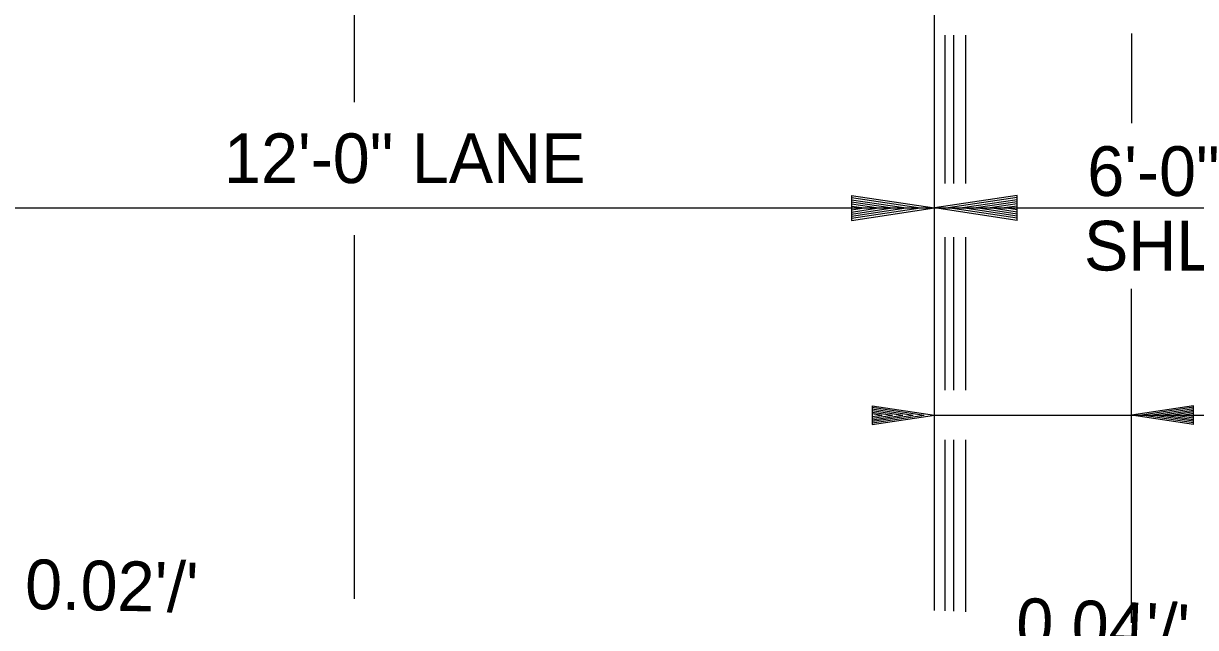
# Model space of a CAD drawing. Extents: x 2263886 to 2266026, y -3122850 to -3121850.
# Drawn here: x 2265509.57 to 2265523.72, y -3122285.03 to -3122277.73 of the extents above; entities that cross this region are included whole.
import ezdxf

# ---------------------------------------------------------------- set-up
doc = ezdxf.new("R2010")
doc.units = 0
doc.layers.add('R_Border Prem', color=7, linetype='Continuous')

msp = doc.modelspace()

# ---------------------------------------------------------------- linework, layer by layer
at = {"layer": 'R_Border Prem'}
for p, q in [((2265513.565, -3122260.962), (2265513.565, -3122278.683)), ((2265520.568, -3122281.934), (2265520.568, -3122276.962)), ((2265520.694, -3122277.875), (2265520.694, -3122279.667)), ((2265520.799, -3122277.875), (2265520.799, -3122279.667)), ((2265520.948, -3122279.667), (2265520.948, -3122277.875)), ((2265522.948, -3122277.857), (2265522.948, -3122278.937)), ((2265519.568, -3122279.812), (2265520.568, -3122279.962)), ((2265519.568, -3122279.812), (2265519.568, -3122280.112)), ((2265519.568, -3122279.837), (2265520.401, -3122279.962)), ((2265519.568, -3122279.863), (2265520.229, -3122279.962)), ((2265519.568, -3122279.888), (2265520.062, -3122279.962)), ((2265521.568, -3122279.812), (2265520.568, -3122279.962)), ((2265521.568, -3122279.837), (2265520.735, -3122279.962)), ((2265521.568, -3122279.863), (2265520.907, -3122279.962)), ((2265521.568, -3122279.888), (2265521.073, -3122279.962)), ((2265521.568, -3122280.112), (2265521.568, -3122279.812)), ((2265508.568, -3122279.962), (2265520.568, -3122279.962)), ((2265519.568, -3122279.914), (2265519.893, -3122279.962)), ((2265519.568, -3122279.939), (2265519.726, -3122279.962)), ((2265519.568, -3122280.112), (2265520.568, -3122279.962)), ((2265519.568, -3122280.011), (2265519.893, -3122279.962)), ((2265519.568, -3122280.062), (2265520.229, -3122279.962)), ((2265519.568, -3122280.087), (2265520.401, -3122279.962)), ((2265519.568, -3122280.037), (2265520.062, -3122279.962)), ((2265519.568, -3122279.986), (2265519.726, -3122279.962)), ((2265521.568, -3122280.112), (2265520.568, -3122279.962)), ((2265520.568, -3122279.962), (2265526.568, -3122279.962)), ((2265521.568, -3122280.087), (2265520.735, -3122279.962)), ((2265521.568, -3122280.062), (2265520.907, -3122279.962)), ((2265521.568, -3122280.037), (2265521.073, -3122279.962)), ((2265521.568, -3122279.913), (2265521.243, -3122279.962)), ((2265521.568, -3122280.011), (2265521.243, -3122279.962)), ((2265521.568, -3122279.939), (2265521.41, -3122279.962)), ((2265521.568, -3122279.986), (2265521.41, -3122279.962)), ((2265513.565, -3122280.29), (2265513.565, -3122283.962)), ((2265520.694, -3122280.315), (2265520.694, -3122282.162)), ((2265520.799, -3122280.315), (2265520.799, -3122282.162)), ((2265520.948, -3122282.162), (2265520.948, -3122280.315)), ((2265522.948, -3122284.972), (2265522.948, -3122280.937)), ((2265520.568, -3122284.822), (2265520.568, -3122281.934)), ((2265519.818, -3122282.35), (2265520.568, -3122282.462)), ((2265519.818, -3122282.35), (2265519.818, -3122282.575)), ((2265519.818, -3122282.368), (2265520.443, -3122282.462)), ((2265519.818, -3122282.388), (2265520.314, -3122282.462)), ((2265519.818, -3122282.406), (2265520.189, -3122282.462)), ((2265519.818, -3122282.426), (2265520.062, -3122282.462)), ((2265519.818, -3122282.445), (2265519.936, -3122282.462)), ((2265523.698, -3122282.35), (2265522.948, -3122282.462)), ((2265523.698, -3122282.368), (2265523.074, -3122282.462)), ((2265523.698, -3122282.388), (2265523.203, -3122282.462)), ((2265523.698, -3122282.406), (2265523.327, -3122282.462)), ((2265523.698, -3122282.425), (2265523.455, -3122282.462)), ((2265523.698, -3122282.445), (2265523.58, -3122282.462)), ((2265523.698, -3122282.575), (2265523.698, -3122282.35)), ((2265519.818, -3122282.575), (2265520.568, -3122282.462)), ((2265519.818, -3122282.499), (2265520.062, -3122282.462)), ((2265519.818, -3122282.537), (2265520.314, -3122282.462)), ((2265519.818, -3122282.556), (2265520.443, -3122282.462)), ((2265519.818, -3122282.518), (2265520.189, -3122282.462)), ((2265519.818, -3122282.48), (2265519.936, -3122282.462)), ((2265520.568, -3122282.462), (2265526.102, -3122282.462)), ((2265523.698, -3122282.575), (2265522.948, -3122282.462)), ((2265523.698, -3122282.556), (2265523.074, -3122282.462)), ((2265523.698, -3122282.537), (2265523.203, -3122282.462)), ((2265523.698, -3122282.518), (2265523.327, -3122282.462)), ((2265523.698, -3122282.499), (2265523.455, -3122282.462)), ((2265523.698, -3122282.48), (2265523.58, -3122282.462)), ((2265520.694, -3122282.762), (2265520.694, -3122284.827)), ((2265520.799, -3122282.762), (2265520.799, -3122284.831)), ((2265520.948, -3122284.837), (2265520.948, -3122282.762)), ((2265513.565, -3122283.962), (2265513.565, -3122284.682))]:
    msp.add_line(p, q, dxfattribs=at)

# ---------------------------------------------------------------- texts
for s, rotation, p in [('12\'-0" LANE', 360, (2265511.993, -3122279.662)), ("0.02'/'", 358.8542, (2265509.586, -3122284.802)), ("0.04'/'", 357.7094, (2265521.546, -3122285.267))]:
    msp.add_text(s, height=0.6, rotation=rotation, dxfattribs=at).set_placement(p)
for s, p in [('6\'-0"', (2265522.414, -3122279.817)), ('SHLD.', (2265522.374, -3122280.717))]:
    msp.add_text(s, height=0.6, dxfattribs=at).set_placement(p)

doc.saveas('drawing.dxf')
